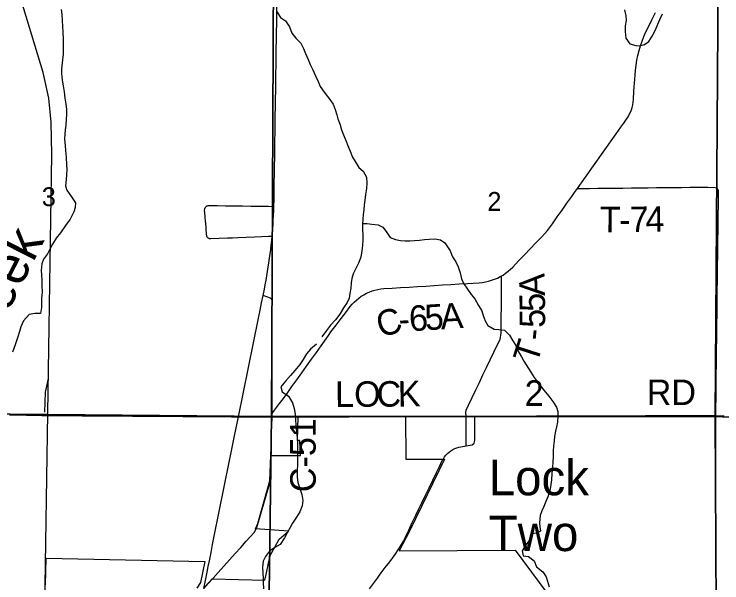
# Model space of a CAD drawing. Extents: x -11.1 to 34, y -3.9 to 22.
# Drawn here: x 4.812 to 6.387, y 16.906 to 18.172 of the extents above; entities that cross this region are included whole.
import ezdxf

# ---------------------------------------------------------------- set-up
doc = ezdxf.new("R2010")
doc.units = 0
for name, color, linetype in [('GM_X_Corporation', 7, 'Continuous'), ('GM_X_County_Road', 7, 'Continuous'), ('GM_X_County_Road_Text', 7, 'Continuous'), ('GM_X_Minor_River', 7, 'Continuous'), ('GM_X_Minor_River_Text', 7, 'Continuous'), ('GM_X_Rail_Line', 7, 'Continuous'), ('GM_X_Section_Text', 7, 'Continuous'), ('GM_X_State_Route', 7, 'Continuous'), ('GM_X_Township_Road', 7, 'Continuous'), ('GM_X_Township_Road_Text', 7, 'Continuous'), ('GM_X_Unincorporated_Text', 7, 'Continuous')]:
    doc.layers.add(name, color=color, linetype=linetype)

msp = doc.modelspace()

# ---------------------------------------------------------------- linework, layer by layer
at = {"layer": 'GM_X_Corporation'}
for points in [[(5.3892, 18.2641), (5.385, 17.2762), (4.3866, 17.2855), (4.3966, 18.2798)], [(5.3892, 18.2641), (6.3791, 18.2511), (6.3727, 17.2765), (5.385, 17.2762)], [(6.3851, 18.2506), (7.3955, 18.2326), (7.3797, 17.2828), (7.3791, 17.2313), (6.3727, 17.2765), (6.3791, 18.2511)], [(5.385, 17.2762), (5.3715, 16.2638), (4.3746, 16.2728), (4.3866, 17.2855)], [(5.385, 17.2762), (6.3727, 17.2765), (6.3775, 16.2691), (5.3715, 16.2638)], [(7.3791, 17.2313), (7.364, 16.2758), (7.3634, 16.2255), (6.3775, 16.2691), (6.3727, 17.2765)]]:
    msp.add_lwpolyline(points, close=True, dxfattribs=at)
for points in [[(5.2332, 16.8936), (5.2529, 16.9154), (5.3703, 16.9122), (5.3729, 16.9248), (5.378, 16.9496), (5.383, 16.9682), (5.3921, 16.9853), (5.4019, 17.0036), (5.4228, 17.0212), (5.3494, 17.0261), (5.3542, 17.0379), (5.381, 17.133), (5.3835, 17.1893), (5.3843, 17.1893), (5.4491, 17.1895), (5.4477, 17.2226), (5.4427, 17.2226), (5.4444, 17.2756), (5.6834, 17.2765), (5.6837, 17.1813), (5.742, 17.1815), (5.7697, 17.1814), (5.6931, 17.0227), (5.669, 16.9771), (5.9275, 16.9789), (6.0538, 16.8089)], [(4.8817, 16.9014), (4.8829, 16.9607), (5.2364, 16.9538), (5.2269, 16.9068), (5.2187, 16.8942)]]:
    msp.add_lwpolyline(points, dxfattribs=at)
at = {"layer": 'GM_X_County_Road'}
for p, q in [((5.3861, 17.2752), (5.3861, 17.2831)), ((5.2541, 16.9156), (5.2547, 16.9163))]:
    msp.add_line(p, q, dxfattribs=at)
for points in [[(6.0659, 17.7835), (6.0767, 17.7987), (6.0874, 17.8139), (6.0982, 17.8291), (6.109, 17.8443), (6.1198, 17.8595), (6.1306, 17.8748), (6.1414, 17.89), (6.1521, 17.9052), (6.1629, 17.9204), (6.1692, 17.9293), (6.1755, 17.9381), (6.1787, 17.943), (6.1815, 17.948), (6.184, 17.9533), (6.1861, 17.9586), (6.1879, 17.9642), (6.1892, 17.9698), (6.1902, 17.9755), (6.1907, 17.9813), (6.1919, 17.9999), (6.1931, 18.018), (6.1942, 18.0361), (6.1951, 18.0471), (6.1965, 18.0581), (6.1983, 18.069), (6.2006, 18.0798), (6.2033, 18.0905), (6.2064, 18.1011), (6.21, 18.1116), (6.214, 18.1219), (6.2184, 18.132), (6.2232, 18.142), (6.2316, 18.1586), (6.2401, 18.1752)], [(5.3861, 17.2831), (5.3917, 17.2906), (5.403, 17.3055), (5.4113, 17.3166), (5.4197, 17.3276), (5.4305, 17.3428), (5.4414, 17.358), (5.4522, 17.3731), (5.463, 17.3883), (5.4739, 17.4035), (5.4847, 17.4186), (5.4955, 17.4338), (5.5064, 17.449), (5.5118, 17.4566), (5.5173, 17.4643), (5.5286, 17.4792), (5.5399, 17.494), (5.55, 17.5074), (5.5602, 17.5207), (5.5644, 17.5259), (5.569, 17.5309), (5.574, 17.5355), (5.5792, 17.5398), (5.5846, 17.5438), (5.5904, 17.5473), (5.5963, 17.5505), (5.6025, 17.5533), (5.6088, 17.5557), (5.6152, 17.5576), (5.6218, 17.5591), (5.6285, 17.5602), (5.6352, 17.5609), (5.6538, 17.562), (5.6724, 17.5632), (5.691, 17.5643), (5.7096, 17.5655), (5.7282, 17.5666), (5.7468, 17.5678), (5.7654, 17.5689), (5.784, 17.5701), (5.8026, 17.5713), (5.8212, 17.5724), (5.8342, 17.5732), (5.8472, 17.574), (5.8542, 17.5747), (5.8612, 17.5758), (5.8681, 17.5773), (5.8748, 17.5793), (5.8815, 17.5816), (5.888, 17.5844), (5.8943, 17.5876), (5.8972, 17.5893), (5.9004, 17.5911), (5.9062, 17.5951), (5.9118, 17.5993), (5.9172, 17.604), (5.9222, 17.6089), (5.9351, 17.6224), (5.9479, 17.6359), (5.9608, 17.6494), (5.9737, 17.6628), (5.9866, 17.6763), (5.9931, 17.6832), (5.9996, 17.69), (6.0104, 17.7052), (6.0212, 17.7204), (6.0319, 17.7356), (6.0427, 17.7508), (6.0535, 17.766), (6.0597, 17.7748), (6.0659, 17.7835)], [(5.3861, 17.2831), (5.3861, 17.5341), (5.3849, 17.5371), (5.3823, 17.5394), (5.3745, 17.5422), (5.366, 17.5452)], [(4.8018, 17.2802), (4.8205, 17.2798), (4.8391, 17.2795), (4.8577, 17.2791), (4.8734, 17.2788), (4.8891, 17.2785), (4.9078, 17.2784), (4.9264, 17.2783), (4.9451, 17.2782), (4.9637, 17.278), (4.9823, 17.2779), (5.001, 17.2778), (5.0196, 17.2777), (5.0383, 17.2775), (5.0569, 17.2774), (5.0755, 17.2773), (5.0942, 17.2772), (5.1128, 17.2771), (5.1315, 17.2769), (5.1501, 17.2768), (5.1687, 17.2767), (5.1874, 17.2765), (5.206, 17.2764), (5.2247, 17.2763), (5.2433, 17.2762), (5.262, 17.276), (5.2806, 17.2759), (5.2959, 17.2758), (5.3113, 17.2757)], [(5.3113, 17.2757), (5.3299, 17.2756), (5.3486, 17.2754), (5.3672, 17.2753), (5.3861, 17.2752)], [(5.3834, 17.1889), (5.384, 17.2075), (5.3846, 17.2261), (5.3851, 17.2448), (5.3856, 17.2584), (5.386, 17.2721), (5.3861, 17.2752)], [(5.3861, 17.2752), (5.4047, 17.2753), (5.4234, 17.2753), (5.4453, 17.2754)], [(5.4453, 17.2754), (5.464, 17.2755), (5.4826, 17.2755), (5.5012, 17.2756), (5.5199, 17.2757), (5.5385, 17.2758), (5.5572, 17.2758), (5.5758, 17.2759), (5.5944, 17.276), (5.6131, 17.276), (5.6317, 17.2761), (5.6504, 17.2762), (5.6668, 17.2762), (5.6832, 17.2763)], [(5.6832, 17.2763), (5.7018, 17.2764), (5.7204, 17.2764), (5.7391, 17.2765), (5.7577, 17.2766), (5.7764, 17.2766), (5.795, 17.2767), (5.8184, 17.2768)], [(5.8184, 17.2768), (5.8374, 17.2769), (5.8561, 17.2769), (5.9006, 17.2771), (5.9192, 17.2772), (5.9378, 17.2773), (5.9565, 17.2773), (5.9751, 17.2774), (5.9938, 17.2775), (6.0124, 17.2775), (6.0311, 17.2776), (6.0497, 17.2777), (6.0683, 17.2777), (6.087, 17.2778), (6.1056, 17.2779), (6.1243, 17.2779), (6.1429, 17.278), (6.1615, 17.2781), (6.1802, 17.2781), (6.2175, 17.2783), (6.2361, 17.2783), (6.2547, 17.2784), (6.292, 17.2785), (6.3293, 17.2787), (6.348, 17.2787), (6.374, 17.2788)], [(6.374, 17.2788), (6.3927, 17.278)], [(5.3522, 17.029), (5.3574, 17.0469), (5.3627, 17.0647), (5.3679, 17.0826), (5.3731, 17.1005), (5.3773, 17.1152), (5.3816, 17.1298), (5.3822, 17.1484), (5.3827, 17.1671), (5.3831, 17.178), (5.3834, 17.1889)], [(5.2547, 16.9163), (5.2665, 16.9294), (5.279, 16.9433), (5.2914, 16.9572), (5.3039, 16.9711), (5.3163, 16.9849), (5.3288, 16.9988), (5.3376, 17.0087), (5.3464, 17.0185), (5.3522, 17.029)], [(5.234, 16.8933), (5.2441, 16.9044), (5.2541, 16.9156)]]:
    msp.add_lwpolyline(points, dxfattribs=at)
at = {"layer": 'GM_X_Minor_River'}
for points in [[(4.9169, 18.1818), (4.9182, 18.1711), (4.919, 18.1578), (4.9199, 18.1441), (4.9204, 18.132), (4.9211, 18.1152), (4.9209, 18.1046), (4.9214, 18.0936), (4.9211, 18.0822), (4.9192, 18.0632), (4.9173, 18.0492), (4.9171, 18.0397), (4.9187, 18.0249), (4.9211, 18.0123), (4.923, 17.9986), (4.9246, 17.9849), (4.927, 17.9711), (4.9286, 17.9601), (4.9284, 17.9491), (4.9277, 17.9373), (4.9267, 17.9248), (4.9257, 17.9142), (4.9247, 17.9047), (4.9241, 17.8941), (4.9256, 17.8785), (4.9265, 17.8682), (4.9277, 17.8537), (4.9288, 17.8358), (4.929, 17.8256), (4.9284, 17.8142), (4.9274, 17.8036), (4.9266, 17.7892), (4.9295, 17.7796), (4.9394, 17.7649), (4.9489, 17.7514), (4.948, 17.7416), (4.9451, 17.7318), (4.9364, 17.7152), (4.9262, 17.701), (4.9148, 17.6846), (4.9058, 17.673), (4.8976, 17.6595), (4.892, 17.6498), (4.8861, 17.6385), (4.8775, 17.6266), (4.8734, 17.616), (4.8723, 17.6008), (4.8729, 17.5913), (4.8734, 17.5788), (4.8739, 17.5677), (4.8743, 17.5529), (4.8729, 17.5393), (4.8726, 17.5283), (4.8732, 17.5187), (4.8706, 17.5055), (4.8577, 17.5054), (4.8455, 17.503), (4.8327, 17.4893), (4.8271, 17.4761), (4.8238, 17.4652), (4.8193, 17.4516), (4.8144, 17.4357), (4.8083, 17.4195)], [(5.396, 18.1779), (5.4051, 18.1644), (5.416, 18.1569), (5.4251, 18.143), (5.4301, 18.1292), (5.4394, 18.118), (5.4505, 18.1071), (5.4559, 18.0948), (5.4606, 18.0841), (5.4667, 18.071), (5.4707, 18.0595), (5.4768, 18.0476), (5.483, 18.0346), (5.4888, 18.0215), (5.4935, 18.0108), (5.5019, 17.998)], [(6.1709, 18.1812), (6.174, 18.1682), (6.1745, 18.1576), (6.1726, 18.1459), (6.1719, 18.1326), (6.1738, 18.1185), (6.1826, 18.1054), (6.1958, 18.1016), (6.2052, 18.1014), (6.2152, 18.1038), (6.2252, 18.1107), (6.2324, 18.1227), (6.2396, 18.1369), (6.2452, 18.1493), (6.2496, 18.1594), (6.2553, 18.1722)], [(5.5019, 17.998), (5.5146, 17.9817), (5.5219, 17.9712), (5.5269, 17.9597), (5.53, 17.9479), (5.5328, 17.9383), (5.5378, 17.9253), (5.5409, 17.9142), (5.5452, 17.9034), (5.5502, 17.8904), (5.5555, 17.8774), (5.5601, 17.8666), (5.5655, 17.8536), (5.5709, 17.8436), (5.5793, 17.8304), (5.5893, 17.8222), (5.5962, 17.8091), (5.5974, 17.7958), (5.5963, 17.7833), (5.5944, 17.7705), (5.5926, 17.758), (5.5915, 17.7474), (5.5901, 17.736), (5.5891, 17.7258), (5.5884, 17.7156), (5.5878, 17.7046), (5.5878, 17.6917), (5.5882, 17.6803), (5.588, 17.6704), (5.5873, 17.6571), (5.5862, 17.6446), (5.5835, 17.631), (5.5782, 17.6171), (5.5734, 17.6074), (5.5666, 17.5939), (5.5637, 17.5837), (5.5623, 17.5735), (5.5612, 17.5618), (5.5594, 17.5497), (5.5576, 17.5398), (5.5532, 17.5301), (5.5449, 17.5182), (5.537, 17.5043), (5.5275, 17.4917), (5.5162, 17.4794), (5.5075, 17.4675), (5.4973, 17.4537)], [(5.5878, 17.7055), (5.598, 17.7054), (5.6082, 17.7044), (5.6226, 17.7029), (5.6327, 17.6977), (5.6404, 17.688), (5.6492, 17.6749), (5.6608, 17.67), (5.6718, 17.6682), (5.6824, 17.6672), (5.6926, 17.6669), (5.7033, 17.6678), (5.7143, 17.669), (5.7257, 17.6698), (5.736, 17.6707), (5.7485, 17.6719), (5.761, 17.6693), (5.7706, 17.6626), (5.7823, 17.6448), (5.788, 17.6314), (5.795, 17.6206), (5.8004, 17.6091), (5.8049, 17.596), (5.808, 17.5823), (5.8134, 17.5715), (5.8214, 17.5595), (5.8291, 17.5479), (5.8376, 17.5378), (5.8459, 17.5236), (5.8528, 17.5116), (5.8559, 17.5013), (5.8606, 17.489), (5.8667, 17.4786), (5.8809, 17.4707), (5.8912, 17.4696), (5.9033, 17.4685), (5.9151, 17.4572), (5.9224, 17.4445), (5.9285, 17.4341), (5.935, 17.4199), (5.9412, 17.4091), (5.9466, 17.3991), (5.9619, 17.3747), (5.9699, 17.3628), (5.9806, 17.3481), (5.9912, 17.3345), (6.0026, 17.3213), (6.011, 17.3093), (6.0191, 17.2969), (6.0222, 17.2873), (6.0227, 17.2771), (6.0216, 17.2638), (6.0194, 17.2532), (6.0173, 17.2434), (6.0151, 17.2321), (6.0141, 17.2222), (6.013, 17.2105), (6.0123, 17.1999), (6.012, 17.1874), (6.0109, 17.1748), (6.0107, 17.1646), (6.0091, 17.1491), (6.008, 17.135), (6.007, 17.1248), (6.0043, 17.1108), (5.9998, 17.0973), (5.9958, 17.0871), (5.9909, 17.0762), (5.9869, 17.0661), (5.9832, 17.0563), (5.9813, 17.04), (5.9822, 17.0305), (5.9834, 17.021), (5.9738, 17.0167), (5.9616, 17.0147), (5.9602, 17.0026), (5.9516, 16.9918), (5.9428, 16.9776), (5.9452, 16.9665), (5.9569, 16.965), (5.97, 16.9552), (5.9749, 16.9418), (5.9887, 16.9308), (5.9967, 16.9192), (6.0034, 16.8973)], [(5.4847, 17.4373), (5.4719, 17.4258), (5.463, 17.4154), (5.4551, 17.403), (5.448, 17.3918), (5.4371, 17.3787), (5.4274, 17.3676), (5.4161, 17.3549), (5.4056, 17.3422), (5.4084, 17.3315), (5.423, 17.3217), (5.4317, 17.307), (5.4356, 17.2944), (5.4376, 17.2811), (5.4385, 17.2685), (5.439, 17.2571), (5.4405, 17.2426), (5.4417, 17.2277), (5.4426, 17.2175), (5.4428, 17.2072), (5.4429, 17.1965), (5.443, 17.1836), (5.4421, 17.1418), (5.4433, 17.1293), (5.4487, 17.1139), (5.4522, 17.1024), (5.4546, 17.0891), (5.4528, 17.0773), (5.4476, 17.0638), (5.4405, 17.0525), (5.4318, 17.039), (5.4263, 17.0293), (5.4204, 17.0188), (5.414, 17.006), (5.4043, 16.9918), (5.392, 16.9848), (5.3804, 16.9767), (5.3714, 16.9648), (5.3666, 16.9546), (5.3652, 16.9413), (5.3656, 16.9269), (5.3662, 16.9173), (5.3667, 16.9067), (5.3668, 16.893)]]:
    msp.add_lwpolyline(points, dxfattribs=at)
at = {"layer": 'GM_X_Rail_Line'}
for points in [[(4.8375, 14.1), (4.84, 14.2474), (4.8556, 15.259), (4.8714, 16.2666), (4.8783, 16.7081), (4.896, 17.8593), (4.8941, 17.9315), (4.8895, 17.9844), (4.8767, 18.0419), (4.6837, 18.6752), (4.6608, 18.751), (4.6471, 18.7984), (4.6397, 18.855), (4.6467, 19.2877), (4.6769, 20.631), (4.6804, 20.8229), (4.6818, 20.9)], [(4.8803, 17.2861), (4.8816, 17.3307), (4.8847, 17.3434), (4.8883, 17.3605)]]:
    msp.add_lwpolyline(points, dxfattribs=at)
at = {"layer": 'GM_X_State_Route'}
for points in [[(5.391, 17.785), (5.3911, 17.7967), (5.3914, 17.8154), (5.3917, 17.834), (5.392, 17.8527), (5.3923, 17.8713), (5.3925, 17.89), (5.3928, 17.9086), (5.3931, 17.9272), (5.3934, 17.9459), (5.3937, 17.9645), (5.3939, 17.9832), (5.3942, 18.0018), (5.3945, 18.0204), (5.3948, 18.0391), (5.3951, 18.0577), (5.3954, 18.0764), (5.3956, 18.095), (5.3959, 18.1136), (5.3962, 18.1323), (5.3965, 18.1509), (5.3968, 18.1696), (5.3971, 18.1882)], [(5.3113, 17.2757), (5.315, 17.294), (5.3187, 17.3122), (5.3224, 17.3305), (5.3261, 17.3488), (5.3298, 17.367), (5.3335, 17.3853), (5.3372, 17.4036), (5.341, 17.4218), (5.3447, 17.4401), (5.3484, 17.4584), (5.3521, 17.4766), (5.3558, 17.4949), (5.3595, 17.5132), (5.3628, 17.5292), (5.366, 17.5452), (5.369, 17.5598), (5.3709, 17.5696), (5.3728, 17.5793), (5.3745, 17.5891), (5.3762, 17.5989), (5.3777, 17.6087), (5.3792, 17.6185), (5.3806, 17.6283), (5.3819, 17.6381), (5.3831, 17.648), (5.3843, 17.6578), (5.3853, 17.6677), (5.3863, 17.6776), (5.3868, 17.6843), (5.3876, 17.6942), (5.3883, 17.7041), (5.3889, 17.714), (5.3895, 17.7239), (5.3899, 17.7339), (5.3902, 17.7438), (5.3906, 17.7595), (5.3909, 17.7781), (5.391, 17.785)], [(5.234, 16.8933), (5.2377, 16.9115), (5.2414, 16.9298), (5.244, 16.9425), (5.2465, 16.9552), (5.2502, 16.9735), (5.2539, 16.9918), (5.2576, 17.01), (5.2613, 17.0283), (5.265, 17.0466), (5.2687, 17.0649), (5.2724, 17.0831), (5.2761, 17.1014), (5.2797, 17.1197), (5.2834, 17.138), (5.2871, 17.1562), (5.2908, 17.1745), (5.2945, 17.1928), (5.2982, 17.211), (5.3019, 17.2293), (5.3056, 17.2476), (5.3084, 17.2616), (5.3113, 17.2757)]]:
    msp.add_lwpolyline(points, dxfattribs=at)
at = {"layer": 'GM_X_Township_Road'}
for points in [[(6.0659, 17.7835), (6.0742, 17.7836), (6.0928, 17.7838), (6.1115, 17.784), (6.1301, 17.7843), (6.1488, 17.7845), (6.1674, 17.7847), (6.186, 17.7849), (6.2047, 17.7851), (6.2233, 17.7854), (6.242, 17.7856), (6.2606, 17.7858), (6.2792, 17.786), (6.2979, 17.7862), (6.3165, 17.7865), (6.3352, 17.7867), (6.3457, 17.7868), (6.3562, 17.7869), (6.3729, 17.7861), (6.3761, 17.7849), (6.3777, 17.7833)], [(6.3755, 16.2665), (6.374, 17.2788), (6.3743, 17.2975), (6.3745, 17.3161), (6.3747, 17.3347), (6.3749, 17.3534), (6.3752, 17.372), (6.3754, 17.3907), (6.3756, 17.4093), (6.3758, 17.4279), (6.3761, 17.4466), (6.3763, 17.4652), (6.3765, 17.4839), (6.3768, 17.5025), (6.377, 17.5212), (6.3772, 17.5398), (6.3774, 17.5584), (6.3777, 17.5771), (6.3779, 17.5957), (6.3781, 17.6144), (6.3783, 17.633), (6.3786, 17.6516), (6.3788, 17.6703), (6.379, 17.6889), (6.3792, 17.7076), (6.3795, 17.7262), (6.3797, 17.7448), (6.3799, 17.7599), (6.3801, 17.7749), (6.3797, 17.7782), (6.3777, 17.7833)], [(5.2378, 17.7084), (5.2369, 17.722), (5.236, 17.7356), (5.2363, 17.7387), (5.2368, 17.7402), (5.2376, 17.7416), (5.2386, 17.7428), (5.2397, 17.7438), (5.241, 17.7447), (5.2425, 17.7453), (5.244, 17.7456), (5.2456, 17.7457), (5.2642, 17.7455), (5.2828, 17.7452), (5.3015, 17.745), (5.3201, 17.7447), (5.3388, 17.7445), (5.3574, 17.7442), (5.3677, 17.7441), (5.378, 17.744), (5.3902, 17.7438)], [(5.2378, 17.7084), (5.2387, 17.6947), (5.2397, 17.681), (5.2399, 17.6794), (5.2404, 17.6778), (5.2412, 17.6764), (5.2422, 17.6751), (5.2434, 17.674), (5.2448, 17.6732), (5.2463, 17.6726), (5.2479, 17.6722), (5.2495, 17.6721), (5.2681, 17.6729), (5.2867, 17.6736), (5.2983, 17.6741), (5.3098, 17.6745), (5.3284, 17.6753), (5.347, 17.676), (5.3626, 17.6766), (5.3781, 17.6773), (5.3863, 17.6776)], [(5.8433, 17.3432), (5.8476, 17.352), (5.8557, 17.3688), (5.8638, 17.3856), (5.8719, 17.4024), (5.88, 17.4192), (5.8869, 17.4335), (5.8938, 17.4478), (5.8962, 17.4623), (5.8963, 17.4809), (5.8965, 17.4996), (5.8966, 17.5182), (5.8968, 17.5369), (5.8969, 17.5555), (5.897, 17.5667), (5.8971, 17.5779), (5.8972, 17.5893)], [(5.8182, 17.2201), (5.8182, 17.2299), (5.8183, 17.2485), (5.8184, 17.2768), (5.8174, 17.2853), (5.8182, 17.2905), (5.8233, 17.3017), (5.8314, 17.3185), (5.8395, 17.3353), (5.8433, 17.3432)], [(5.8181, 17.2112), (5.8314, 17.213), (5.836, 17.2171), (5.8372, 17.2229), (5.8373, 17.2415), (5.8374, 17.269), (5.8374, 17.2769)], [(5.7669, 17.181), (5.7676, 17.1823), (5.7703, 17.1864), (5.7733, 17.1902), (5.7767, 17.1938), (5.7803, 17.197), (5.7842, 17.1999), (5.7883, 17.2025), (5.7927, 17.2047), (5.7972, 17.2065), (5.8019, 17.208), (5.8066, 17.209), (5.8181, 17.2112), (5.8182, 17.2201)], [(5.6656, 16.977), (5.6702, 16.9841), (5.6745, 16.9914), (5.6785, 16.9989), (5.6823, 17.0065), (5.6903, 17.0233), (5.6983, 17.0402), (5.7062, 17.057), (5.7127, 17.0707), (5.7192, 17.0844), (5.7275, 17.1012), (5.7357, 17.1179), (5.7439, 17.1346), (5.7521, 17.1513), (5.7587, 17.1647), (5.7652, 17.1781), (5.7669, 17.181)], [(5.6028, 16.8925), (5.614, 16.9075), (5.6205, 16.9163), (5.6271, 16.9252), (5.6383, 16.9401), (5.6481, 16.953), (5.6578, 16.966), (5.6618, 16.9714), (5.6656, 16.977)]]:
    msp.add_lwpolyline(points, dxfattribs=at)

# ---------------------------------------------------------------- texts
at = {"layer": 'GM_X_County_Road_Text'}
for s, height, rotation, p in [('6', 0.0568, 3.733, (5.6927, 17.4656)), ('5', 0.0568, 3.7395, (5.7277, 17.4679)), ('A', 0.0568, 3.7365, (5.7626, 17.4701)), ('C', 0.0568, 16.6204, (5.628, 17.4513)), ('-', 0.0568, 3.7261, (5.6694, 17.4641)), ('L', 0.0568, 0.2636, (5.5264, 17.2975)), ('O', 0.0568, 0.2656, (5.5689, 17.2977)), ('C', 0.0568, 0.2693, (5.6189, 17.298)), ('K', 0.0568, 1.0083, (5.6664, 17.2982)), ('2', 0.0568, 0, (5.9485, 17.3)), ('RD', 0.05682, 0, (6.2202, 17.3017)), ('C-51', 0.05682, 90.0982, (5.4834, 17.1078))]:
    msp.add_text(s, height=height, rotation=rotation, dxfattribs=at).set_placement(p)
at = {"layer": 'GM_X_Minor_River_Text'}
msp.add_text('Creek', height=0.08523, rotation=63.05, dxfattribs=at).set_placement((4.7422, 17.3976))
at = {"layer": 'GM_X_Section_Text'}
for s, p in [('3', (4.8735, 17.7444)), ('2', (5.8656, 17.7339))]:
    msp.add_text(s, height=0.0419, rotation=0, dxfattribs=at).set_placement(p)
at = {"layer": 'GM_X_Township_Road_Text'}
for s, rotation, p in [('T', 359.3721, (6.1153, 17.6866)), ('7', 0.8208, (6.1827, 17.6863)), ('4', 0.9117, (6.2178, 17.6868)), ('-', 0.4819, (6.159, 17.6861)), ('A', 91.1595, (5.9936, 17.5449)), ('5', 91.0313, (5.9942, 17.5098)), ('5', 89.8892, (5.9941, 17.4735)), ('-', 83.8877, (5.9913, 17.4438)), ('T', 72.0848, (5.9756, 17.3909))]:
    msp.add_text(s, height=0.0568, rotation=rotation, dxfattribs=at).set_placement(p)
at = {"layer": 'GM_X_Unincorporated_Text'}
for s, p in [('Lock', (5.8685, 17.101)), ('Two', (5.8685, 16.9768))]:
    msp.add_text(s, height=0.07898, rotation=0, dxfattribs=at).set_placement(p)

doc.saveas('drawing.dxf')
